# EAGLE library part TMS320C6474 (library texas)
TMS320C6474 Multicore Digital Signal Processor Auto generated by make-symbol-device-package-bsdl.ulp Rev. 29 Source: sprm335.bsd http://focus.ti.com/lit/ds/symlink/tms320c6474.pdf Connect-List generated from TMS320C6474.DEV Variant '' with connect-device-split-symbol-03.ulp
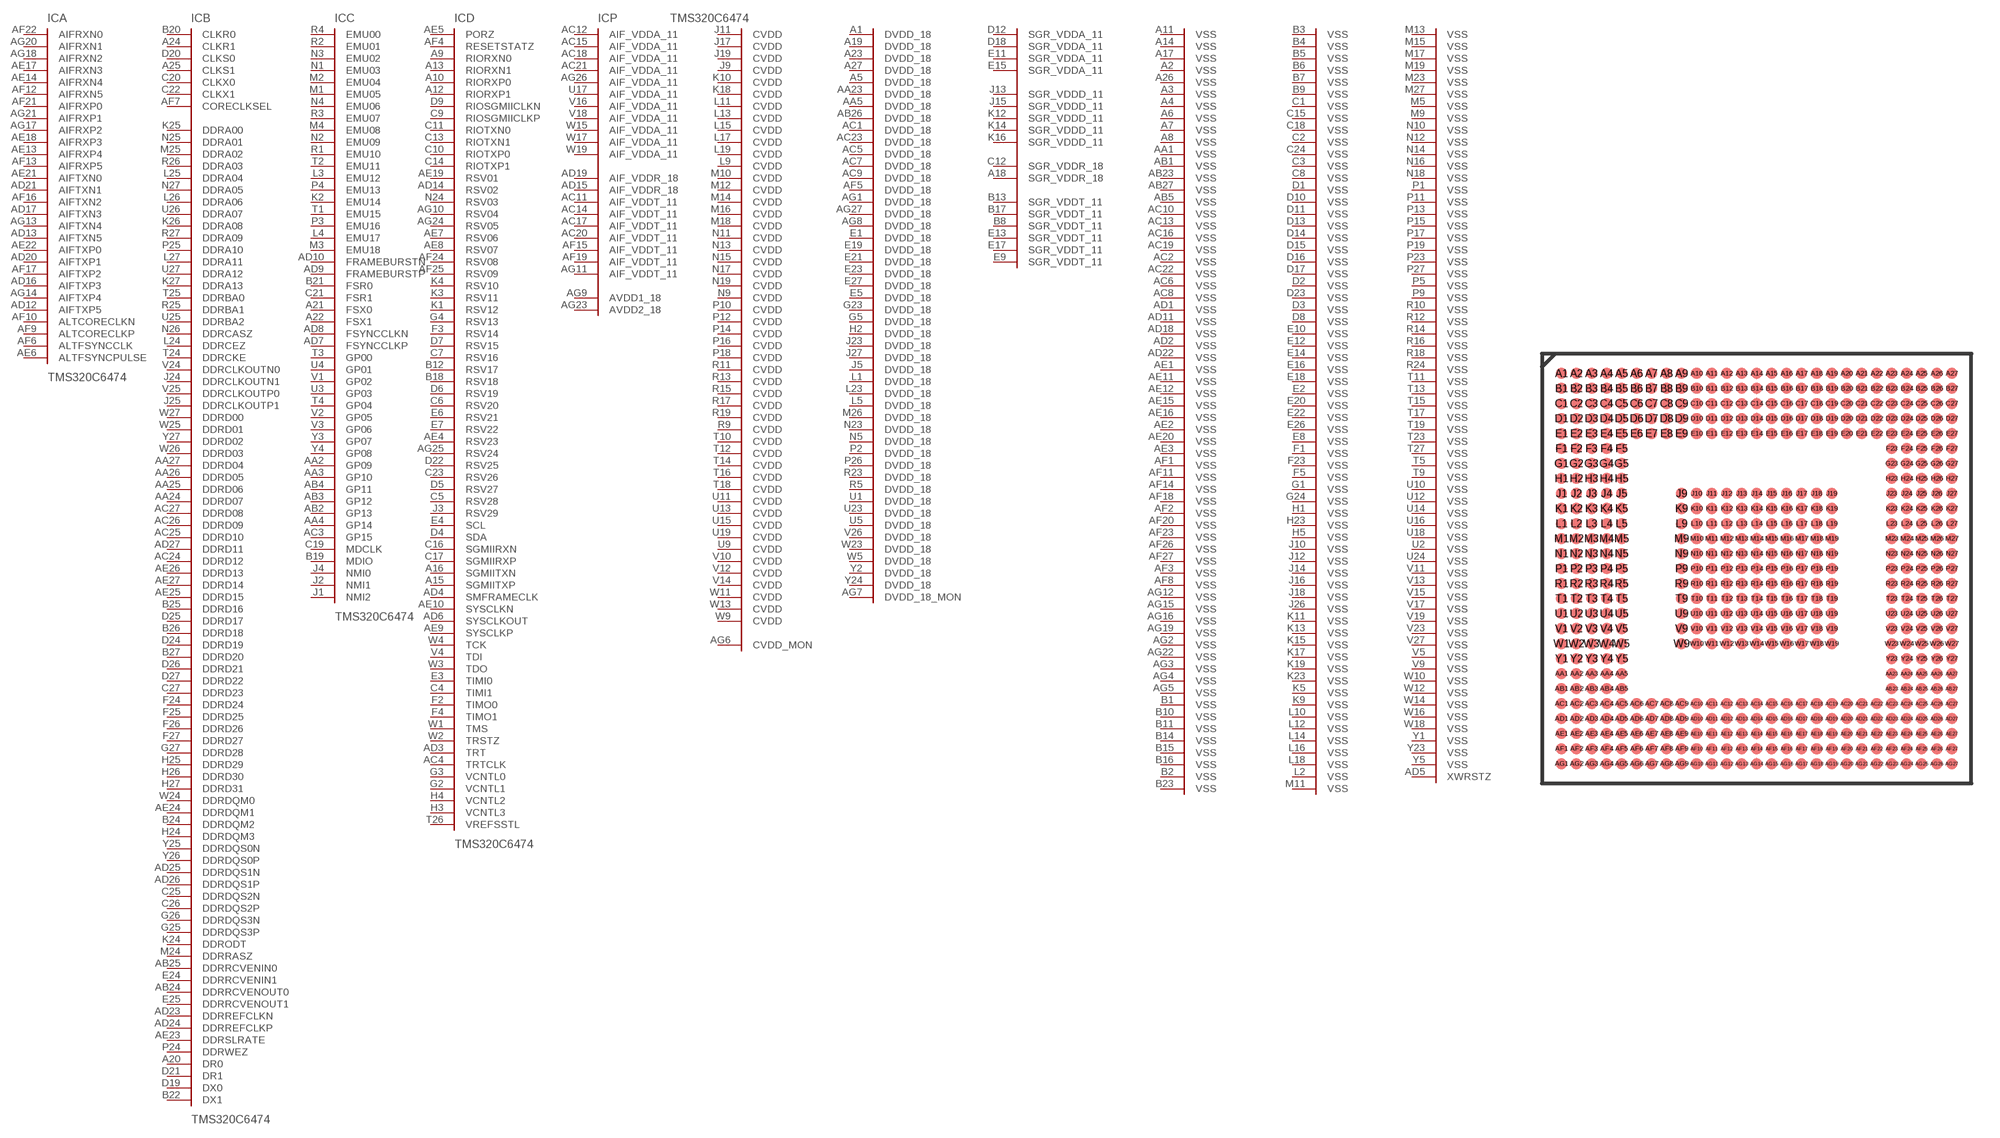
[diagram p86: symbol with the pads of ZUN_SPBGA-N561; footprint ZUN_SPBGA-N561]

Designator prefix IC; gates A=TMS320C6474-A B=TMS320C6474-B C=TMS320C6474-C D=TMS320C6474-D P=TMS320C6474-P

## TMS320C6474 (OC_FARNELL: 1791956; OC_NEWARK: unknown)  [ZUN_SPBGA-N561]
A1  P:DVDD_18  pas
A2  P:VSS  pas
A3  P:VSS  pas
A4  P:VSS  pas
A5  P:DVDD_18  pas
A6  P:VSS  pas
A7  P:VSS  pas
A8  P:VSS  pas
A9  D:RIORXN0  pas
A10  D:RIORXP0  pas
A11  P:VSS  pas
A12  D:RIORXP1  pas
A13  D:RIORXN1  pas
A14  P:VSS  pas
A15  D:SGMIITXP  pas
A16  D:SGMIITXN  pas
A17  P:VSS  pas
A18  P:SGR_VDDR_18  pas
A19  P:DVDD_18  pas
A20  B:DR0  pas
A21  C:FSX0  pas
A22  C:FSX1  pas
A23  P:DVDD_18  pas
A24  B:CLKR1  pas
A25  B:CLKS1  pas
A26  P:VSS  pas
A27  P:DVDD_18  pas
AA1  P:VSS  pas
AA2  C:GP09  pas
AA3  C:GP10  pas
AA4  C:GP14  pas
AA5  P:DVDD_18  pas
AA23  P:DVDD_18  pas
AA24  B:DDRD07  pas
AA25  B:DDRD06  pas
AA26  B:DDRD05  pas
AA27  B:DDRD04  pas
AB1  P:VSS  pas
AB2  C:GP13  pas
AB3  C:GP12  pas
AB4  C:GP11  pas
AB5  P:VSS  pas
AB23  P:VSS  pas
AB24  B:DDRRCVENOUT0  pas
AB25  B:DDRRCVENIN0  pas
AB26  P:DVDD_18  pas
AB27  P:VSS  pas
AC1  P:DVDD_18  pas
AC2  P:VSS  pas
AC3  C:GP15  pas
AC4  D:TRTCLK  pas
AC5  P:DVDD_18  pas
AC6  P:VSS  pas
AC7  P:DVDD_18  pas
AC8  P:VSS  pas
AC9  P:DVDD_18  pas
AC10  P:VSS  pas
AC11  P:AIF_VDDT_11  pas
AC12  P:AIF_VDDA_11  pas
AC13  P:VSS  pas
AC14  P:AIF_VDDT_11  pas
AC15  P:AIF_VDDA_11  pas
AC16  P:VSS  pas
AC17  P:AIF_VDDT_11  pas
AC18  P:AIF_VDDA_11  pas
AC19  P:VSS  pas
AC20  P:AIF_VDDT_11  pas
AC21  P:AIF_VDDA_11  pas
AC22  P:VSS  pas
AC23  P:DVDD_18  pas
AC24  B:DDRD12  pas
AC25  B:DDRD10  pas
AC26  B:DDRD09  pas
AC27  B:DDRD08  pas
AD1  P:VSS  pas
AD2  P:VSS  pas
AD3  D:TRT  pas
AD4  D:SMFRAMECLK  pas
AD5  P:XWRSTZ  pas
AD6  D:SYSCLKOUT  pas
AD7  C:FSYNCCLKP  pas
AD8  C:FSYNCCLKN  pas
AD9  C:FRAMEBURSTP  pas
AD10  C:FRAMEBURSTN  pas
AD11  P:VSS  pas
AD12  A:AIFTXP5  pas
AD13  A:AIFTXN5  pas
AD14  D:RSV02  pas
AD15  P:AIF_VDDR_18  pas
AD16  A:AIFTXP3  pas
AD17  A:AIFTXN3  pas
AD18  P:VSS  pas
AD19  P:AIF_VDDR_18  pas
AD20  A:AIFTXP1  pas
AD21  A:AIFTXN1  pas
AD22  P:VSS  pas
AD23  B:DDRREFCLKN  pas
AD24  B:DDRREFCLKP  pas
AD25  B:DDRDQS1N  pas
AD26  B:DDRDQS1P  pas
AD27  B:DDRD11  pas
AE1  P:VSS  pas
AE2  P:VSS  pas
AE3  P:VSS  pas
AE4  D:RSV23  pas
AE5  D:PORZ  pas
AE6  A:ALTFSYNCPULSE  pas
AE7  D:RSV06  pas
AE8  D:RSV07  pas
AE9  D:SYSCLKP  pas
AE10  D:SYSCLKN  pas
AE11  P:VSS  pas
AE12  P:VSS  pas
AE13  A:AIFRXP4  pas
AE14  A:AIFRXN4  pas
AE15  P:VSS  pas
AE16  P:VSS  pas
AE17  A:AIFRXN3  pas
AE18  A:AIFRXP3  pas
AE19  D:RSV01  pas
AE20  P:VSS  pas
AE21  A:AIFTXN0  pas
AE22  A:AIFTXP0  pas
AE23  B:DDRSLRATE  pas
AE24  B:DDRDQM1  pas
AE25  B:DDRD15  pas
AE26  B:DDRD13  pas
AE27  B:DDRD14  pas
AF1  P:VSS  pas
AF2  P:VSS  pas
AF3  P:VSS  pas
AF4  D:RESETSTATZ  pas
AF5  P:DVDD_18  pas
AF6  A:ALTFSYNCCLK  pas
AF7  B:CORECLKSEL  pas
AF8  P:VSS  pas
AF9  A:ALTCORECLKP  pas
AF10  A:ALTCORECLKN  pas
AF11  P:VSS  pas
AF12  A:AIFRXN5  pas
AF13  A:AIFRXP5  pas
AF14  P:VSS  pas
AF15  P:AIF_VDDT_11  pas
AF16  A:AIFTXN2  pas
AF17  A:AIFTXP2  pas
AF18  P:VSS  pas
AF19  P:AIF_VDDT_11  pas
AF20  P:VSS  pas
AF21  A:AIFRXP0  pas
AF22  A:AIFRXN0  pas
AF23  P:VSS  pas
AF24  D:RSV08  pas
AF25  D:RSV09  pas
AF26  P:VSS  pas
AF27  P:VSS  pas
AG1  P:DVDD_18  pas
AG2  P:VSS  pas
AG3  P:VSS  pas
AG4  P:VSS  pas
AG5  P:VSS  pas
AG6  P:CVDD_MON  pas
AG7  P:DVDD_18_MON  pas
AG8  P:DVDD_18  pas
AG9  P:AVDD1_18  pas
AG10  D:RSV04  pas
AG11  P:AIF_VDDT_11  pas
AG12  P:VSS  pas
AG13  A:AIFTXN4  pas
AG14  A:AIFTXP4  pas
AG15  P:VSS  pas
AG16  P:VSS  pas
AG17  A:AIFRXP2  pas
AG18  A:AIFRXN2  pas
AG19  P:VSS  pas
AG20  A:AIFRXN1  pas
AG21  A:AIFRXP1  pas
AG22  P:VSS  pas
AG23  P:AVDD2_18  pas
AG24  D:RSV05  pas
AG25  D:RSV24  pas
AG26  P:AIF_VDDA_11  pas
AG27  P:DVDD_18  pas
B1  P:VSS  pas
B2  P:VSS  pas
B3  P:VSS  pas
B4  P:VSS  pas
B5  P:VSS  pas
B6  P:VSS  pas
B7  P:VSS  pas
B8  P:SGR_VDDT_11  pas
B9  P:VSS  pas
B10  P:VSS  pas
B11  P:VSS  pas
B12  D:RSV17  pas
B13  P:SGR_VDDT_11  pas
B14  P:VSS  pas
B15  P:VSS  pas
B16  P:VSS  pas
B17  P:SGR_VDDT_11  pas
B18  D:RSV18  pas
B19  C:MDIO  pas
B20  B:CLKR0  pas
B21  C:FSR0  pas
B22  B:DX1  pas
B23  P:VSS  pas
B24  B:DDRDQM2  pas
B25  B:DDRD16  pas
B26  B:DDRD18  pas
B27  B:DDRD20  pas
C1  P:VSS  pas
C2  P:VSS  pas
C3  P:VSS  pas
C4  D:TIMI1  pas
C5  D:RSV28  pas
C6  D:RSV20  pas
C7  D:RSV16  pas
C8  P:VSS  pas
C9  D:RIOSGMIICLKP  pas
C10  D:RIOTXP0  pas
C11  D:RIOTXN0  pas
C12  P:SGR_VDDR_18  pas
C13  D:RIOTXN1  pas
C14  D:RIOTXP1  pas
C15  P:VSS  pas
C16  D:SGMIIRXN  pas
C17  D:SGMIIRXP  pas
C18  P:VSS  pas
C19  C:MDCLK  pas
C20  B:CLKX0  pas
C21  C:FSR1  pas
C22  B:CLKX1  pas
C23  D:RSV26  pas
C24  P:VSS  pas
C25  B:DDRDQS2N  pas
C26  B:DDRDQS2P  pas
C27  B:DDRD23  pas
D1  P:VSS  pas
D2  P:VSS  pas
D3  P:VSS  pas
D4  D:SDA  pas
D5  D:RSV27  pas
D6  D:RSV19  pas
D7  D:RSV15  pas
D8  P:VSS  pas
D9  D:RIOSGMIICLKN  pas
D10  P:VSS  pas
D11  P:VSS  pas
D12  P:SGR_VDDA_11  pas
D13  P:VSS  pas
D14  P:VSS  pas
D15  P:VSS  pas
D16  P:VSS  pas
D17  P:VSS  pas
D18  P:SGR_VDDA_11  pas
D19  B:DX0  pas
D20  B:CLKS0  pas
D21  B:DR1  pas
D22  D:RSV25  pas
D23  P:VSS  pas
D24  B:DDRD19  pas
D25  B:DDRD17  pas
D26  B:DDRD21  pas
D27  B:DDRD22  pas
E1  P:DVDD_18  pas
E2  P:VSS  pas
E3  D:TIMI0  pas
E4  D:SCL  pas
E5  P:DVDD_18  pas
E6  D:RSV21  pas
E7  D:RSV22  pas
E8  P:VSS  pas
E9  P:SGR_VDDT_11  pas
E10  P:VSS  pas
E11  P:SGR_VDDA_11  pas
E12  P:VSS  pas
E13  P:SGR_VDDT_11  pas
E14  P:VSS  pas
E15  P:SGR_VDDA_11  pas
E16  P:VSS  pas
E17  P:SGR_VDDT_11  pas
E18  P:VSS  pas
E19  P:DVDD_18  pas
E20  P:VSS  pas
E21  P:DVDD_18  pas
E22  P:VSS  pas
E23  P:DVDD_18  pas
E24  B:DDRRCVENIN1  pas
E25  B:DDRRCVENOUT1  pas
E26  P:VSS  pas
E27  P:DVDD_18  pas
F1  P:VSS  pas
F2  D:TIMO0  pas
F3  D:RSV14  pas
F4  D:TIMO1  pas
F5  P:VSS  pas
F23  P:VSS  pas
F24  B:DDRD24  pas
F25  B:DDRD25  pas
F26  B:DDRD26  pas
F27  B:DDRD27  pas
G1  P:VSS  pas
G2  D:VCNTL1  pas
G3  D:VCNTL0  pas
G4  D:RSV13  pas
G5  P:DVDD_18  pas
G23  P:DVDD_18  pas
G24  P:VSS  pas
G25  B:DDRDQS3P  pas
G26  B:DDRDQS3N  pas
G27  B:DDRD28  pas
H1  P:VSS  pas
H2  P:DVDD_18  pas
H3  D:VCNTL3  pas
H4  D:VCNTL2  pas
H5  P:VSS  pas
H23  P:VSS  pas
H24  B:DDRDQM3  pas
H25  B:DDRD29  pas
H26  B:DDRD30  pas
H27  B:DDRD31  pas
J1  C:NMI2  pas
J2  C:NMI1  pas
J3  D:RSV29  pas
J4  C:NMI0  pas
J5  P:DVDD_18  pas
J9  P:CVDD  pas
J10  P:VSS  pas
J11  P:CVDD  pas
J12  P:VSS  pas
J13  P:SGR_VDDD_11  pas
J14  P:VSS  pas
J15  P:SGR_VDDD_11  pas
J16  P:VSS  pas
J17  P:CVDD  pas
J18  P:VSS  pas
J19  P:CVDD  pas
J23  P:DVDD_18  pas
J24  B:DDRCLKOUTN1  pas
J25  B:DDRCLKOUTP1  pas
J26  P:VSS  pas
J27  P:DVDD_18  pas
K1  D:RSV12  pas
K2  C:EMU14  pas
K3  D:RSV11  pas
K4  D:RSV10  pas
K5  P:VSS  pas
K9  P:VSS  pas
K10  P:CVDD  pas
K11  P:VSS  pas
K12  P:SGR_VDDD_11  pas
K13  P:VSS  pas
K14  P:SGR_VDDD_11  pas
K15  P:VSS  pas
K16  P:SGR_VDDD_11  pas
K17  P:VSS  pas
K18  P:CVDD  pas
K19  P:VSS  pas
K23  P:VSS  pas
K24  B:DDRODT  pas
K25  B:DDRA00  pas
K26  B:DDRA08  pas
K27  B:DDRA13  pas
L1  P:DVDD_18  pas
L2  P:VSS  pas
L3  C:EMU12  pas
L4  C:EMU17  pas
L5  P:DVDD_18  pas
L9  P:CVDD  pas
L10  P:VSS  pas
L11  P:CVDD  pas
L12  P:VSS  pas
L13  P:CVDD  pas
L14  P:VSS  pas
L15  P:CVDD  pas
L16  P:VSS  pas
L17  P:CVDD  pas
L18  P:VSS  pas
L19  P:CVDD  pas
L23  P:DVDD_18  pas
L24  B:DDRCEZ  pas
L25  B:DDRA04  pas
L26  B:DDRA06  pas
L27  B:DDRA11  pas
M1  C:EMU05  pas
M2  C:EMU04  pas
M3  C:EMU18  pas
M4  C:EMU08  pas
M5  P:VSS  pas
M9  P:VSS  pas
M10  P:CVDD  pas
M11  P:VSS  pas
M12  P:CVDD  pas
M13  P:VSS  pas
M14  P:CVDD  pas
M15  P:VSS  pas
M16  P:CVDD  pas
M17  P:VSS  pas
M18  P:CVDD  pas
M19  P:VSS  pas
M23  P:VSS  pas
M24  B:DDRRASZ  pas
M25  B:DDRA02  pas
M26  P:DVDD_18  pas
M27  P:VSS  pas
N1  C:EMU03  pas
N2  C:EMU09  pas
N3  C:EMU02  pas
N4  C:EMU06  pas
N5  P:DVDD_18  pas
N9  P:CVDD  pas
N10  P:VSS  pas
N11  P:CVDD  pas
N12  P:VSS  pas
N13  P:CVDD  pas
N14  P:VSS  pas
N15  P:CVDD  pas
N16  P:VSS  pas
N17  P:CVDD  pas
N18  P:VSS  pas
N19  P:CVDD  pas
N23  P:DVDD_18  pas
N24  D:RSV03  pas
N25  B:DDRA01  pas
N26  B:DDRCASZ  pas
N27  B:DDRA05  pas
P1  P:VSS  pas
P2  P:DVDD_18  pas
P3  C:EMU16  pas
P4  C:EMU13  pas
P5  P:VSS  pas
P9  P:VSS  pas
P10  P:CVDD  pas
P11  P:VSS  pas
P12  P:CVDD  pas
P13  P:VSS  pas
P14  P:CVDD  pas
P15  P:VSS  pas
P16  P:CVDD  pas
P17  P:VSS  pas
P18  P:CVDD  pas
P19  P:VSS  pas
P23  P:VSS  pas
P24  B:DDRWEZ  pas
P25  B:DDRA10  pas
P26  P:DVDD_18  pas
P27  P:VSS  pas
R1  C:EMU10  pas
R2  C:EMU01  pas
R3  C:EMU07  pas
R4  C:EMU00  pas
R5  P:DVDD_18  pas
R9  P:CVDD  pas
R10  P:VSS  pas
R11  P:CVDD  pas
R12  P:VSS  pas
R13  P:CVDD  pas
R14  P:VSS  pas
R15  P:CVDD  pas
R16  P:VSS  pas
R17  P:CVDD  pas
R18  P:VSS  pas
R19  P:CVDD  pas
R23  P:DVDD_18  pas
R24  P:VSS  pas
R25  B:DDRBA1  pas
R26  B:DDRA03  pas
R27  B:DDRA09  pas
T1  C:EMU15  pas
T2  C:EMU11  pas
T3  C:GP00  pas
T4  C:GP04  pas
T5  P:VSS  pas
T9  P:VSS  pas
T10  P:CVDD  pas
T11  P:VSS  pas
T12  P:CVDD  pas
T13  P:VSS  pas
T14  P:CVDD  pas
T15  P:VSS  pas
T16  P:CVDD  pas
T17  P:VSS  pas
T18  P:CVDD  pas
T19  P:VSS  pas
T23  P:VSS  pas
T24  B:DDRCKE  pas
T25  B:DDRBA0  pas
T26  D:VREFSSTL  pas
T27  P:VSS  pas
U1  P:DVDD_18  pas
U2  P:VSS  pas
U3  C:GP03  pas
U4  C:GP01  pas
U5  P:DVDD_18  pas
U9  P:CVDD  pas
U10  P:VSS  pas
U11  P:CVDD  pas
U12  P:VSS  pas
U13  P:CVDD  pas
U14  P:VSS  pas
U15  P:CVDD  pas
U16  P:VSS  pas
U17  P:AIF_VDDA_11  pas
U18  P:VSS  pas
U19  P:CVDD  pas
U23  P:DVDD_18  pas
U24  P:VSS  pas
U25  B:DDRBA2  pas
U26  B:DDRA07  pas
U27  B:DDRA12  pas
V1  C:GP02  pas
V2  C:GP05  pas
V3  C:GP06  pas
V4  D:TDI  pas
V5  P:VSS  pas
V9  P:VSS  pas
V10  P:CVDD  pas
V11  P:VSS  pas
V12  P:CVDD  pas
V13  P:VSS  pas
V14  P:CVDD  pas
V15  P:VSS  pas
V16  P:AIF_VDDA_11  pas
V17  P:VSS  pas
V18  P:AIF_VDDA_11  pas
V19  P:VSS  pas
V23  P:VSS  pas
V24  B:DDRCLKOUTN0  pas
V25  B:DDRCLKOUTP0  pas
V26  P:DVDD_18  pas
V27  P:VSS  pas
W1  D:TMS  pas
W2  D:TRSTZ  pas
W3  D:TDO  pas
W4  D:TCK  pas
W5  P:DVDD_18  pas
W9  P:CVDD  pas
W10  P:VSS  pas
W11  P:CVDD  pas
W12  P:VSS  pas
W13  P:CVDD  pas
W14  P:VSS  pas
W15  P:AIF_VDDA_11  pas
W16  P:VSS  pas
W17  P:AIF_VDDA_11  pas
W18  P:VSS  pas
W19  P:AIF_VDDA_11  pas
W23  P:DVDD_18  pas
W24  B:DDRDQM0  pas
W25  B:DDRD01  pas
W26  B:DDRD03  pas
W27  B:DDRD00  pas
Y1  P:VSS  pas
Y2  P:DVDD_18  pas
Y3  C:GP07  pas
Y4  C:GP08  pas
Y5  P:VSS  pas
Y23  P:VSS  pas
Y24  P:DVDD_18  pas
Y25  B:DDRDQS0N  pas
Y26  B:DDRDQS0P  pas
Y27  B:DDRD02  pas

## Footprint ZUN_SPBGA-N561 (pad centres in mm)
ZUN (S-PBGA-N561) OLASTIC BALL GRID ARRAY Auto generated by make-symbol-device-package-bsdl.ulp Rev. 29 Source: sprm335.bsd http://focus.ti.com/lit/ds/symlink/tms320c6474.pdf
smd 0.6 x 0.6: A1 -10.4,10.4; A2 -9.6,10.4; A3 -8.8,10.4; A4 -8,10.4; A5 -7.2,10.4; A6 -6.4,10.4; A7 -5.6,10.4; A8 -4.8,10.4; A9 -4,10.4; A10 -3.2,10.4; A11 -2.4,10.4; A12 -1.6,10.4; A13 -0.8,10.4; A14 0,10.4; A15 0.8,10.4; A16 1.6,10.4; A17 2.4,10.4; A18 3.2,10.4; A19 4,10.4; A20 4.8,10.4; A21 5.6,10.4; A22 6.4,10.4; A23 7.2,10.4; A24 8,10.4; A25 8.8,10.4; A26 9.6,10.4; A27 10.4,10.4; AA1 -10.4,-5.6; AA2 -9.6,-5.6; AA3 -8.8,-5.6; AA4 -8,-5.6; AA5 -7.2,-5.6; AA23 7.2,-5.6; AA24 8,-5.6; AA25 8.8,-5.6; AA26 9.6,-5.6; AA27 10.4,-5.6; AB1 -10.4,-6.4; AB2 -9.6,-6.4; AB3 -8.8,-6.4; AB4 -8,-6.4; AB5 -7.2,-6.4; AB23 7.2,-6.4; AB24 8,-6.4; AB25 8.8,-6.4; AB26 9.6,-6.4; AB27 10.4,-6.4; AC1 -10.4,-7.2; AC2 -9.6,-7.2; AC3 -8.8,-7.2; AC4 -8,-7.2; AC5 -7.2,-7.2; AC6 -6.4,-7.2; AC7 -5.6,-7.2; AC8 -4.8,-7.2; AC9 -4,-7.2; AC10 -3.2,-7.2; AC11 -2.4,-7.2; AC12 -1.6,-7.2; AC13 -0.8,-7.2; AC14 0,-7.2; AC15 0.8,-7.2; AC16 1.6,-7.2; AC17 2.4,-7.2; AC18 3.2,-7.2; AC19 4,-7.2; AC20 4.8,-7.2; AC21 5.6,-7.2; AC22 6.4,-7.2; AC23 7.2,-7.2; AC24 8,-7.2; AC25 8.8,-7.2; AC26 9.6,-7.2; AC27 10.4,-7.2; AD1 -10.4,-8; AD2 -9.6,-8; AD3 -8.8,-8; AD4 -8,-8; AD5 -7.2,-8; AD6 -6.4,-8; AD7 -5.6,-8; AD8 -4.8,-8; AD9 -4,-8; AD10 -3.2,-8; AD11 -2.4,-8; AD12 -1.6,-8; AD13 -0.8,-8; AD14 0,-8; AD15 0.8,-8; AD16 1.6,-8; AD17 2.4,-8; AD18 3.2,-8; AD19 4,-8; AD20 4.8,-8; AD21 5.6,-8; AD22 6.4,-8; AD23 7.2,-8; AD24 8,-8; AD25 8.8,-8; AD26 9.6,-8; AD27 10.4,-8; AE1 -10.4,-8.8; AE2 -9.6,-8.8; AE3 -8.8,-8.8; AE4 -8,-8.8; AE5 -7.2,-8.8; AE6 -6.4,-8.8; AE7 -5.6,-8.8; AE8 -4.8,-8.8; AE9 -4,-8.8; AE10 -3.2,-8.8; AE11 -2.4,-8.8; AE12 -1.6,-8.8; AE13 -0.8,-8.8; AE14 0,-8.8; AE15 0.8,-8.8; AE16 1.6,-8.8; AE17 2.4,-8.8; AE18 3.2,-8.8; AE19 4,-8.8; AE20 4.8,-8.8; AE21 5.6,-8.8; AE22 6.4,-8.8; AE23 7.2,-8.8; AE24 8,-8.8; AE25 8.8,-8.8; AE26 9.6,-8.8; AE27 10.4,-8.8; AF1 -10.4,-9.6; AF2 -9.6,-9.6; AF3 -8.8,-9.6; AF4 -8,-9.6; AF5 -7.2,-9.6; AF6 -6.4,-9.6; AF7 -5.6,-9.6; AF8 -4.8,-9.6; AF9 -4,-9.6; AF10 -3.2,-9.6; AF11 -2.4,-9.6; AF12 -1.6,-9.6; AF13 -0.8,-9.6; AF14 0,-9.6; AF15 0.8,-9.6; AF16 1.6,-9.6; AF17 2.4,-9.6; AF18 3.2,-9.6; AF19 4,-9.6; AF20 4.8,-9.6; AF21 5.6,-9.6; AF22 6.4,-9.6; AF23 7.2,-9.6; AF24 8,-9.6; AF25 8.8,-9.6; AF26 9.6,-9.6; AF27 10.4,-9.6; AG1 -10.4,-10.4; AG2 -9.6,-10.4; AG3 -8.8,-10.4; AG4 -8,-10.4; AG5 -7.2,-10.4; AG6 -6.4,-10.4; AG7 -5.6,-10.4; AG8 -4.8,-10.4; AG9 -4,-10.4; AG10 -3.2,-10.4; AG11 -2.4,-10.4; AG12 -1.6,-10.4; AG13 -0.8,-10.4; AG14 0,-10.4; AG15 0.8,-10.4; AG16 1.6,-10.4; AG17 2.4,-10.4; AG18 3.2,-10.4; AG19 4,-10.4; AG20 4.8,-10.4; AG21 5.6,-10.4; AG22 6.4,-10.4; AG23 7.2,-10.4; AG24 8,-10.4; AG25 8.8,-10.4; AG26 9.6,-10.4; AG27 10.4,-10.4; B1 -10.4,9.6; B2 -9.6,9.6; B3 -8.8,9.6; B4 -8,9.6; B5 -7.2,9.6; B6 -6.4,9.6; B7 -5.6,9.6; B8 -4.8,9.6; B9 -4,9.6; B10 -3.2,9.6; B11 -2.4,9.6; B12 -1.6,9.6; B13 -0.8,9.6; B14 0,9.6; B15 0.8,9.6; B16 1.6,9.6; B17 2.4,9.6; B18 3.2,9.6; B19 4,9.6; B20 4.8,9.6; B21 5.6,9.6; B22 6.4,9.6; B23 7.2,9.6; B24 8,9.6; B25 8.8,9.6; B26 9.6,9.6; B27 10.4,9.6; C1 -10.4,8.8; C2 -9.6,8.8; C3 -8.8,8.8; C4 -8,8.8; C5 -7.2,8.8; C6 -6.4,8.8; C7 -5.6,8.8; C8 -4.8,8.8; C9 -4,8.8; C10 -3.2,8.8; C11 -2.4,8.8; C12 -1.6,8.8; C13 -0.8,8.8; C14 0,8.8; C15 0.8,8.8; C16 1.6,8.8; C17 2.4,8.8; C18 3.2,8.8; C19 4,8.8; C20 4.8,8.8; C21 5.6,8.8; C22 6.4,8.8; C23 7.2,8.8; C24 8,8.8; C25 8.8,8.8; C26 9.6,8.8; C27 10.4,8.8; D1 -10.4,8; D2 -9.6,8; D3 -8.8,8; D4 -8,8; D5 -7.2,8; D6 -6.4,8; D7 -5.6,8; D8 -4.8,8; D9 -4,8; D10 -3.2,8; D11 -2.4,8; D12 -1.6,8; D13 -0.8,8; D14 0,8; D15 0.8,8; D16 1.6,8; D17 2.4,8; D18 3.2,8; D19 4,8; D20 4.8,8; D21 5.6,8; D22 6.4,8; D23 7.2,8; D24 8,8; D25 8.8,8; D26 9.6,8; D27 10.4,8; E1 -10.4,7.2; E2 -9.6,7.2; E3 -8.8,7.2; E4 -8,7.2; E5 -7.2,7.2; E6 -6.4,7.2; E7 -5.6,7.2; E8 -4.8,7.2; E9 -4,7.2; E10 -3.2,7.2; E11 -2.4,7.2; E12 -1.6,7.2; E13 -0.8,7.2; E14 0,7.2; E15 0.8,7.2; E16 1.6,7.2; E17 2.4,7.2; E18 3.2,7.2; E19 4,7.2; E20 4.8,7.2; E21 5.6,7.2; E22 6.4,7.2; E23 7.2,7.2; E24 8,7.2; E25 8.8,7.2; E26 9.6,7.2; E27 10.4,7.2; F1 -10.4,6.4; F2 -9.6,6.4; F3 -8.8,6.4; F4 -8,6.4; F5 -7.2,6.4; F23 7.2,6.4; F24 8,6.4; F25 8.8,6.4; F26 9.6,6.4; F27 10.4,6.4; G1 -10.4,5.6; G2 -9.6,5.6; G3 -8.8,5.6; G4 -8,5.6; G5 -7.2,5.6; G23 7.2,5.6; G24 8,5.6; G25 8.8,5.6; G26 9.6,5.6; G27 10.4,5.6; H1 -10.4,4.8; H2 -9.6,4.8; H3 -8.8,4.8; H4 -8,4.8; H5 -7.2,4.8; H23 7.2,4.8; H24 8,4.8; H25 8.8,4.8; H26 9.6,4.8; H27 10.4,4.8; J1 -10.4,4; J2 -9.6,4; J3 -8.8,4; J4 -8,4; J5 -7.2,4; J9 -4,4; J10 -3.2,4; J11 -2.4,4; J12 -1.6,4; J13 -0.8,4; J14 0,4; J15 0.8,4; J16 1.6,4; J17 2.4,4; J18 3.2,4; J19 4,4; J23 7.2,4; J24 8,4; J25 8.8,4; J26 9.6,4; J27 10.4,4; K1 -10.4,3.2; K2 -9.6,3.2; K3 -8.8,3.2; K4 -8,3.2; K5 -7.2,3.2; K9 -4,3.2; K10 -3.2,3.2; K11 -2.4,3.2; K12 -1.6,3.2; K13 -0.8,3.2; K14 0,3.2; K15 0.8,3.2; K16 1.6,3.2; K17 2.4,3.2; K18 3.2,3.2; K19 4,3.2; K23 7.2,3.2; K24 8,3.2; K25 8.8,3.2; K26 9.6,3.2; K27 10.4,3.2; L1 -10.4,2.4; L2 -9.6,2.4; L3 -8.8,2.4; L4 -8,2.4; L5 -7.2,2.4; L9 -4,2.4; L10 -3.2,2.4; L11 -2.4,2.4; L12 -1.6,2.4; L13 -0.8,2.4; L14 0,2.4; L15 0.8,2.4; L16 1.6,2.4; L17 2.4,2.4; L18 3.2,2.4; L19 4,2.4; L23 7.2,2.4; L24 8,2.4; L25 8.8,2.4; L26 9.6,2.4; L27 10.4,2.4; M1 -10.4,1.6; M2 -9.6,1.6; M3 -8.8,1.6; M4 -8,1.6; M5 -7.2,1.6; M9 -4,1.6; M10 -3.2,1.6; M11 -2.4,1.6; M12 -1.6,1.6; M13 -0.8,1.6; M14 0,1.6; M15 0.8,1.6; M16 1.6,1.6; M17 2.4,1.6; M18 3.2,1.6; M19 4,1.6; M23 7.2,1.6; M24 8,1.6; M25 8.8,1.6; M26 9.6,1.6; M27 10.4,1.6; N1 -10.4,0.8; N2 -9.6,0.8; N3 -8.8,0.8; N4 -8,0.8; N5 -7.2,0.8; N9 -4,0.8; N10 -3.2,0.8; N11 -2.4,0.8; N12 -1.6,0.8; N13 -0.8,0.8; N14 0,0.8; N15 0.8,0.8; N16 1.6,0.8; N17 2.4,0.8; N18 3.2,0.8; N19 4,0.8; N23 7.2,0.8; N24 8,0.8; N25 8.8,0.8; N26 9.6,0.8; N27 10.4,0.8; P1 -10.4,0; P2 -9.6,0; P3 -8.8,0; P4 -8,0; P5 -7.2,0; P9 -4,0; P10 -3.2,0; P11 -2.4,0; P12 -1.6,0; P13 -0.8,0; P14 0,0; P15 0.8,0; P16 1.6,0; P17 2.4,0; P18 3.2,0; P19 4,0; P23 7.2,0; P24 8,0; P25 8.8,0; P26 9.6,0; P27 10.4,0; R1 -10.4,-0.8; R2 -9.6,-0.8; R3 -8.8,-0.8; R4 -8,-0.8; R5 -7.2,-0.8; R9 -4,-0.8; R10 -3.2,-0.8; R11 -2.4,-0.8; R12 -1.6,-0.8; R13 -0.8,-0.8; R14 0,-0.8; R15 0.8,-0.8; R16 1.6,-0.8; R17 2.4,-0.8; R18 3.2,-0.8; R19 4,-0.8; R23 7.2,-0.8; R24 8,-0.8; R25 8.8,-0.8; R26 9.6,-0.8; R27 10.4,-0.8; T1 -10.4,-1.6; T2 -9.6,-1.6; T3 -8.8,-1.6; T4 -8,-1.6; T5 -7.2,-1.6; T9 -4,-1.6; T10 -3.2,-1.6; T11 -2.4,-1.6; T12 -1.6,-1.6; T13 -0.8,-1.6; T14 0,-1.6; T15 0.8,-1.6; T16 1.6,-1.6; T17 2.4,-1.6; T18 3.2,-1.6; T19 4,-1.6; T23 7.2,-1.6; T24 8,-1.6; T25 8.8,-1.6; T26 9.6,-1.6; T27 10.4,-1.6; U1 -10.4,-2.4; U2 -9.6,-2.4; U3 -8.8,-2.4; U4 -8,-2.4; U5 -7.2,-2.4; U9 -4,-2.4; U10 -3.2,-2.4; U11 -2.4,-2.4; U12 -1.6,-2.4; U13 -0.8,-2.4; U14 0,-2.4; U15 0.8,-2.4; U16 1.6,-2.4; U17 2.4,-2.4; U18 3.2,-2.4; U19 4,-2.4; U23 7.2,-2.4; U24 8,-2.4; U25 8.8,-2.4; U26 9.6,-2.4; U27 10.4,-2.4; V1 -10.4,-3.2; V2 -9.6,-3.2; V3 -8.8,-3.2; V4 -8,-3.2; V5 -7.2,-3.2; V9 -4,-3.2; V10 -3.2,-3.2; V11 -2.4,-3.2; V12 -1.6,-3.2; V13 -0.8,-3.2; V14 0,-3.2; V15 0.8,-3.2; V16 1.6,-3.2; V17 2.4,-3.2; V18 3.2,-3.2; V19 4,-3.2; V23 7.2,-3.2; V24 8,-3.2; V25 8.8,-3.2; V26 9.6,-3.2; V27 10.4,-3.2; W1 -10.4,-4; W2 -9.6,-4; W3 -8.8,-4; W4 -8,-4; W5 -7.2,-4; W9 -4,-4; W10 -3.2,-4; W11 -2.4,-4; W12 -1.6,-4; W13 -0.8,-4; W14 0,-4; W15 0.8,-4; W16 1.6,-4; W17 2.4,-4; W18 3.2,-4; W19 4,-4; W23 7.2,-4; W24 8,-4; W25 8.8,-4; W26 9.6,-4; W27 10.4,-4; Y1 -10.4,-4.8; Y2 -9.6,-4.8; Y3 -8.8,-4.8; Y4 -8,-4.8; Y5 -7.2,-4.8; Y23 7.2,-4.8; Y24 8,-4.8; Y25 8.8,-4.8; Y26 9.6,-4.8; Y27 10.4,-4.8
